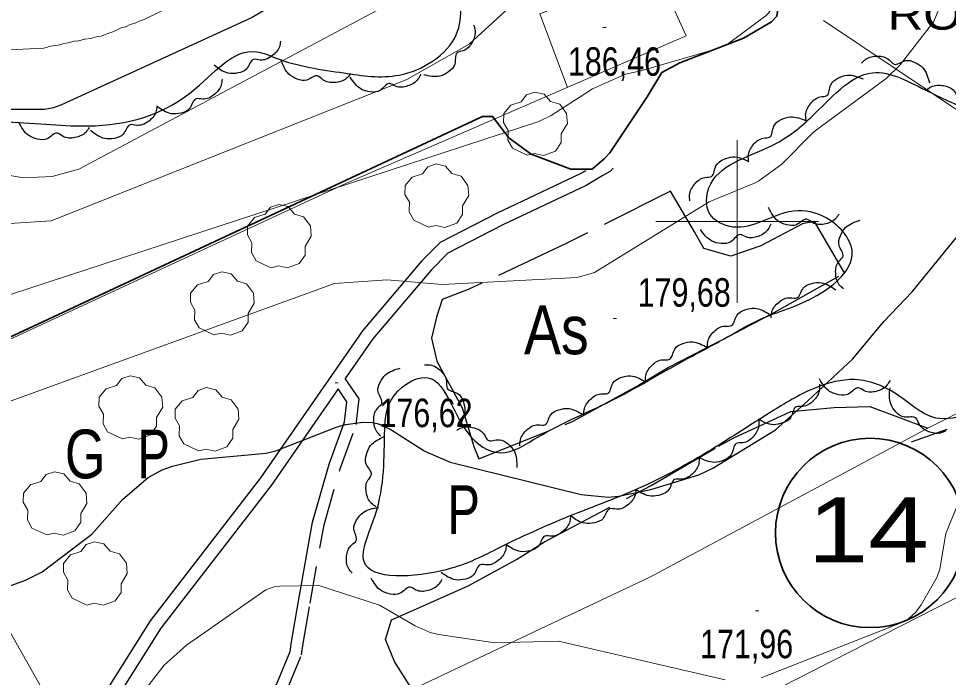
# Model space of a CAD drawing. Extents: x 483847 to 488453, y 4383581 to 4386795.
# Drawn here: x 484279 to 484564.9, y 4384859.8 to 4385062.3 of the extents above; entities that cross this region are included whole.
import ezdxf
from ezdxf.enums import TextEntityAlignment as Align

# ---------------------------------------------------------------- set-up
doc = ezdxf.new("R2010")
doc.units = 0
doc.header["$LTSCALE"] = 3.8
doc.linetypes.add('LONG_DASHED', pattern=[7.5, 6, -1.5])
doc.linetypes.add('MEDIUM_DASHED', pattern=[4.5, 3, -1.5])
for name, color, linetype, lineweight in [('1', 7, 'Continuous', 13), ('13', 7, 'Continuous', 25), ('25', 7, 'LONG_DASHED', 25), ('27', 7, 'Continuous', 25), ('29', 7, 'Continuous', 13), ('38', 7, 'Continuous', 25), ('51', 7, 'Continuous', 13), ('6', 7, 'Continuous', 35), ('7', 7, 'Continuous', 13), ('8', 7, 'Continuous', 25), ('9', 7, 'Continuous', 13)]:
    doc.layers.add(name, color=color, linetype=linetype, lineweight=lineweight)
doc.layers.add('31', color=7, linetype='Continuous')
doc.layers.add('5', color=7, linetype='Continuous')

msp = doc.modelspace()

# ---------------------------------------------------------------- linework, layer by layer
at = {"layer": '1'}
for p, q in [((484500, 4385025), (484500, 4384975)), ((484475, 4385000), (484525, 4385000))]:
    msp.add_line(p, q, dxfattribs=at)
at = {"layer": '25'}
for points in [[(484407.47, 4384970.58), (484405.96, 4384964.15), (484407.6, 4384957), (484415.4, 4384942.72), (484419.03, 4384930.85), (484420.57, 4384926.99), (484449.29, 4384938.49), (484469.13, 4384949.39), (484478.74, 4384955.04), (484497.73, 4384964.85), (484511.37, 4384971.98), (484532.95, 4384984.19), (484523.74, 4384999.93), (484520.07, 4384999.29), (484507.21, 4384992.53), (484497.98, 4384989.36), (484489.73, 4384991.68), (484486.87, 4384996.75), (484479.45, 4385009.25), (484447.21, 4384993.1), (484417.29, 4384979.02)], [(484417.29, 4384979.02), (484409.3, 4384975.94), (484407.47, 4384970.58)], [(484400.03, 4384856.08), (484394.58, 4384864.7), (484391.81, 4384871.43), (484393.69, 4384877.52), (484401.36, 4384880.88), (484417.27, 4384888.02), (484432.06, 4384896.02), (484440.68, 4384901.54), (484473.49, 4384918.81), (484494.24, 4384930.91), (484498.88, 4384933.47), (484516.48, 4384941.57), (484529.75, 4384942.8), (484540.79, 4384943.06), (484558.57, 4384936.42)]]:
    msp.add_lwpolyline(points, dxfattribs=at)
at = {"layer": '27'}
for points in [[(484126.09, 4384902.79), (484170.42, 4384940.62), (484186.72, 4384951.71), (484191.28, 4384949.75), (484195.85, 4384942.58), (484195.2, 4384850.61), (484198.46, 4384849.31), (484203.02, 4384849.96), (484206.93, 4384851.91), (484210.19, 4384864.31), (484210.19, 4384911.92), (484211.5, 4384943.23), (484214.1, 4384965.41), (484221.93, 4384987.58), (484217.36, 4384992.8), (484210.19, 4384992.8), (484135.22, 4384984.97), (484130.65, 4384988.89), (484126.09, 4384997.37), (484121.53, 4385047.59), (484126.09, 4385059.33), (484133.91, 4385067.16), (484151.52, 4385069.77), (484197.15, 4385061.94), (484225.84, 4385054.77), (484236.92, 4385050.2), (484251.92, 4385040.42), (484272.13, 4385031.28), (484285.82, 4385029.98), (484298.2, 4385029.33), (484332.11, 4385039.76), (484352.32, 4385052.16), (484358.18, 4385050.2), (484379.05, 4385045.63), (484396, 4385044.98), (484413.6, 4385057.38), (484413.6, 4385076.29), (484415.56, 4385110.21), (484421.42, 4385117.38), (484434.46, 4385125.86), (484452.06, 4385127.17), (484517.26, 4385131.08), (484535.51, 4385145.43), (484539.43, 4385153.26), (484534.21, 4385163.04), (484527.69, 4385172.17), (484530.3, 4385183.26), (484560.29, 4385234.79), (484583.76, 4385251.75), (484588.32, 4385252.4), (484664.6, 4385247.83), (484699.15, 4385252.4), (484722.1, 4385262.06)], [(484418.91, 4385060.4), (484419.36, 4385058.69), (484418.44, 4385055.01), (484415.75, 4385052.47), (484413.82, 4385051.77), (484413.13, 4385048.28), (484411.25, 4385045.96), (484408.53, 4385044.63), (484403.59, 4385045.04)], [(484359.54, 4385055.43), (484359.22, 4385053.69), (484356.82, 4385050.75), (484353.31, 4385049.59), (484351.27, 4385049.78), (484349.16, 4385046.91), (484346.47, 4385045.62), (484343.45, 4385045.56), (484339.15, 4385048.03)], [(484380.98, 4385045.23), (484379.79, 4385043.91), (484376.2, 4385042.68), (484372.61, 4385043.53), (484370.96, 4385044.76), (484367.67, 4385043.44), (484364.7, 4385043.75), (484362.1, 4385045.29), (484359.73, 4385049.65)], [(484538.21, 4385048.6), (484539.5, 4385049.83), (484543.16, 4385050.8), (484546.68, 4385049.68), (484548.23, 4385048.33), (484551.62, 4385049.42), (484554.56, 4385048.89), (484557.04, 4385047.16), (484559.08, 4385042.64)], [(484585.59, 4384948.21), (484580.97, 4384945.58), (484559.8, 4384939.88), (484549.69, 4384946.4), (484536.11, 4384951.35), (484524.15, 4384948.87), (484511.2, 4384941.93), (484493.5, 4384930.76), (484470.97, 4384918.5), (484448.03, 4384909.24), (484426.95, 4384899.71), (484410.49, 4384892.92), (484385.23, 4384895.42), (484388.62, 4384909.57), (484391.63, 4384936.1), (484393.56, 4384945.05), (484404.24, 4384952.03), (484417.14, 4384934.99), (484427.13, 4384928.88), (484438.84, 4384933.79), (484461.12, 4384944.82), (484483.93, 4384957.41), (484496.79, 4384964.37), (484506.7, 4384969.76), (484524.49, 4384977.21), (484535.34, 4384990.46), (484526.45, 4385001.52), (484515.95, 4385002.96), (484498.76, 4384998.27), (484491.46, 4385002.45), (484491.28, 4385010.27), (484510.27, 4385023.11), (484522.64, 4385031.97), (484541.56, 4385045.7), (484558.82, 4385039.91), (484572.59, 4385033.52), (484597.25, 4385020.22), (484607.27, 4385012.89), (484618.82, 4385004.61), (484624.36, 4385000.79), (484636.37, 4384994.07), (484662.16, 4385005.98), (484666.23, 4385010.44), (484675.39, 4385021.46), (484682.04, 4385029.89), (484691.36, 4385035.38), (484695.06, 4385038.96)], [(484341.58, 4385043.71), (484341.34, 4385041.95), (484339.08, 4385038.91), (484335.63, 4385037.59), (484333.58, 4385037.67), (484331.6, 4385034.72), (484328.98, 4385033.3), (484325.96, 4385033.1), (484321.55, 4385035.37)], [(484402.63, 4385045.27), (484401.8, 4385043.7), (484398.63, 4385041.62), (484394.94, 4385041.57), (484393.04, 4385042.36), (484390.17, 4385040.26), (484387.22, 4385039.83), (484384.32, 4385040.68), (484380.95, 4385044.33)], [(484521.2, 4385030.91), (484521.01, 4385032.67), (484522.48, 4385036.17), (484525.52, 4385038.27), (484527.53, 4385038.68), (484528.74, 4385042.02), (484530.95, 4385044.03), (484533.83, 4385044.94), (484538.66, 4385043.79)], [(484558.14, 4385040.38), (484559.61, 4385041.38), (484563.38, 4385041.73), (484566.67, 4385040.05), (484567.98, 4385038.47), (484571.49, 4385038.98), (484574.31, 4385037.97), (484576.47, 4385035.86), (484577.73, 4385031.07)], [(484321.57, 4385035.35), (484321.25, 4385033.6), (484318.85, 4385030.66), (484315.34, 4385029.51), (484313.3, 4385029.69), (484311.19, 4385026.82), (484308.5, 4385025.52), (484305.48, 4385025.47), (484301.18, 4385027.93)], [(484503.54, 4385018.29), (484503.38, 4385020.06), (484504.9, 4385023.54), (484507.97, 4385025.59), (484509.99, 4385025.97), (484511.25, 4385029.29), (484513.49, 4385031.27), (484516.38, 4385032.14), (484521.19, 4385030.92)], [(484300.77, 4385028.91), (484299.76, 4385027.45), (484296.37, 4385025.75), (484292.7, 4385026.12), (484290.9, 4385027.12), (484287.81, 4385025.37), (484284.83, 4385025.28), (484282.04, 4385026.46), (484279.12, 4385030.47)], [(484485.44, 4385006.32), (484485.32, 4385008.1), (484486.94, 4385011.53), (484490.06, 4385013.5), (484492.09, 4385013.82), (484493.44, 4385017.11), (484495.73, 4385019.02), (484498.65, 4385019.81), (484503.43, 4385018.46)], [(484531.22, 4385002.21), (484530.18, 4385000.77), (484526.75, 4384999.15), (484523.09, 4384999.61), (484521.32, 4385000.65), (484518.18, 4384998.98), (484515.2, 4384998.96), (484512.45, 4385000.21), (484509.62, 4385004.28)], [(484532.63, 4384979.27), (484531.36, 4384980.5), (484530.24, 4384984.13), (484531.21, 4384987.69), (484532.5, 4384989.29), (484531.28, 4384992.63), (484531.68, 4384995.59), (484533.31, 4384998.14), (484537.74, 4385000.36)], [(484510.29, 4384999.16), (484509.51, 4384997.56), (484506.41, 4384995.38), (484502.72, 4384995.21), (484500.8, 4384995.93), (484498, 4384993.74), (484495.06, 4384993.21), (484492.14, 4384993.97), (484488.65, 4384997.5)], [(484510.37, 4384970.36), (484510.6, 4384972.12), (484512.83, 4384975.19), (484516.26, 4384976.55), (484518.31, 4384976.48), (484520.25, 4384979.46), (484522.87, 4384980.91), (484525.88, 4384981.14), (484530.32, 4384978.92)], [(484490.85, 4384961.14), (484490.91, 4384962.92), (484492.85, 4384966.18), (484496.15, 4384967.84), (484498.2, 4384967.97), (484499.86, 4384971.11), (484502.32, 4384972.79), (484505.3, 4384973.3), (484509.92, 4384971.5)], [(484471.81, 4384950.73), (484471.86, 4384952.51), (484473.78, 4384955.78), (484477.07, 4384957.46), (484479.12, 4384957.6), (484480.76, 4384960.75), (484483.21, 4384962.45), (484486.19, 4384962.97), (484490.82, 4384961.2)], [(484390.41, 4384934.03), (484389.19, 4384935.32), (484388.22, 4384938.99), (484389.34, 4384942.5), (484390.69, 4384944.05), (484389.6, 4384947.44), (484390.13, 4384950.38), (484391.86, 4384952.86), (484396.38, 4384954.9)], [(484403.78, 4384955.9), (484405.56, 4384955.88), (484408.86, 4384954.02), (484410.6, 4384950.77), (484410.77, 4384948.72), (484413.95, 4384947.13), (484415.69, 4384944.7), (484416.26, 4384941.73), (484414.57, 4384937.07)], [(484452.82, 4384940.23), (484452.87, 4384942.01), (484454.78, 4384945.28), (484458.07, 4384946.97), (484460.12, 4384947.11), (484461.75, 4384950.27), (484464.21, 4384951.97), (484467.18, 4384952.49), (484471.82, 4384950.72)], [(484546.95, 4384951.14), (484546.02, 4384949.63), (484542.73, 4384947.75), (484539.04, 4384947.93), (484537.2, 4384948.84), (484534.2, 4384946.93), (484531.23, 4384946.68), (484528.38, 4384947.72), (484525.26, 4384951.57)], [(484525.27, 4384949.95), (484525.25, 4384948.17), (484523.37, 4384944.87), (484520.11, 4384943.14), (484518.07, 4384942.98), (484516.47, 4384939.8), (484514.04, 4384938.07), (484511.07, 4384937.5), (484506.41, 4384939.21)], [(484564.13, 4384935.62), (484562.49, 4384934.95), (484558.72, 4384935.41), (484555.87, 4384937.75), (484554.92, 4384939.57), (484551.38, 4384939.82), (484548.84, 4384941.39), (484547.17, 4384943.91), (484546.95, 4384948.87)], [(484433.15, 4384931.05), (484433.29, 4384932.82), (484435.39, 4384935.98), (484438.76, 4384937.48), (484440.82, 4384937.5), (484442.63, 4384940.56), (484445.17, 4384942.12), (484448.18, 4384942.48), (484452.7, 4384940.45)], [(484506.57, 4384938.96), (484506.62, 4384937.18), (484504.89, 4384933.81), (484501.7, 4384931.94), (484499.66, 4384931.69), (484498.2, 4384928.45), (484495.85, 4384926.61), (484492.9, 4384925.92), (484488.18, 4384927.43)], [(484413.72, 4384935.75), (484415.28, 4384936.58), (484419.08, 4384936.52), (484422.16, 4384934.49), (484423.29, 4384932.78), (484426.84, 4384932.9), (484429.53, 4384931.6), (484431.45, 4384929.26), (484432.19, 4384924.36)], [(484388.89, 4384912.28), (484387.47, 4384913.35), (484385.91, 4384916.81), (484386.45, 4384920.46), (484387.52, 4384922.21), (484385.9, 4384925.37), (484385.95, 4384928.36), (484387.25, 4384931.09), (484391.38, 4384933.83)], [(484488.24, 4384927.29), (484488.14, 4384925.52), (484486.11, 4384922.31), (484482.77, 4384920.74), (484480.72, 4384920.67), (484478.98, 4384917.57), (484476.47, 4384915.96), (484473.47, 4384915.53), (484468.9, 4384917.46)], [(484468.85, 4384917.57), (484468.58, 4384915.81), (484466.28, 4384912.8), (484462.81, 4384911.53), (484460.76, 4384911.65), (484458.74, 4384908.72), (484456.1, 4384907.34), (484453.08, 4384907.19), (484448.7, 4384909.52)], [(484381.56, 4384891.95), (484380.47, 4384893.36), (484379.88, 4384897.11), (484381.36, 4384900.49), (484382.86, 4384901.89), (484382.13, 4384905.37), (484382.96, 4384908.24), (484384.93, 4384910.53), (484389.64, 4384912.09)], [(484448.69, 4384909.54), (484448.5, 4384907.77), (484446.32, 4384904.66), (484442.91, 4384903.25), (484440.86, 4384903.28), (484438.97, 4384900.27), (484436.38, 4384898.78), (484433.37, 4384898.5), (484428.9, 4384900.64)], [(484428.93, 4384900.56), (484428.71, 4384898.79), (484426.47, 4384895.73), (484423.03, 4384894.39), (484420.98, 4384894.46), (484419.03, 4384891.49), (484416.41, 4384890.05), (484413.4, 4384889.83), (484408.97, 4384892.06)], [(484409.11, 4384889.93), (484408.19, 4384888.42), (484404.9, 4384886.53), (484401.21, 4384886.69), (484399.37, 4384887.59), (484396.38, 4384885.67), (484393.4, 4384885.41), (484390.56, 4384886.44), (484387.42, 4384890.28)]]:
    msp.add_spline(points, degree=3, dxfattribs=at)
at = {"layer": '29'}
for points in [[(484435.38, 4385020.34), (484430.84, 4385022.46), (484429.43, 4385025), (484429.53, 4385027.98), (484428.16, 4385030.39), (484428.2, 4385033.14), (484430.36, 4385035.74), (484433.55, 4385036.74), (484435.2, 4385038.93), (484437.77, 4385039.76), (484440.63, 4385039.11), (484442.58, 4385036.84), (484445.39, 4385036.02), (484447.52, 4385033.17), (484447.76, 4385030.04), (484445.88, 4385026.89), (484445.88, 4385024.21), (484444.06, 4385021.6), (484440.44, 4385020.26), (484437.67, 4385020.89)], [(484405.05, 4384998.23), (484400.51, 4385000.35), (484399.1, 4385002.89), (484399.2, 4385005.87), (484397.83, 4385008.28), (484397.87, 4385011.03), (484400.03, 4385013.63), (484403.22, 4385014.63), (484404.87, 4385016.82), (484407.44, 4385017.65), (484410.3, 4385017), (484412.25, 4385014.73), (484415.06, 4385013.91), (484417.19, 4385011.06), (484417.43, 4385007.93), (484415.55, 4385004.78), (484415.55, 4385002.1), (484413.73, 4384999.49), (484410.11, 4384998.15), (484407.34, 4384998.78)], [(484356.63, 4384985.77), (484352.09, 4384987.89), (484350.68, 4384990.43), (484350.78, 4384993.41), (484349.41, 4384995.82), (484349.45, 4384998.57), (484351.61, 4385001.17), (484354.8, 4385002.17), (484356.45, 4385004.36), (484359.02, 4385005.19), (484361.88, 4385004.54), (484363.83, 4385002.27), (484366.64, 4385001.45), (484368.77, 4384998.6), (484369.01, 4384995.47), (484367.13, 4384992.32), (484367.13, 4384989.64), (484365.31, 4384987.03), (484361.69, 4384985.69), (484358.92, 4384986.32)], [(484339.1, 4384965.12), (484334.56, 4384967.24), (484333.15, 4384969.78), (484333.25, 4384972.76), (484331.88, 4384975.17), (484331.92, 4384977.92), (484334.08, 4384980.52), (484337.27, 4384981.52), (484338.92, 4384983.71), (484341.49, 4384984.54), (484344.35, 4384983.89), (484346.3, 4384981.62), (484349.11, 4384980.8), (484351.24, 4384977.95), (484351.48, 4384974.82), (484349.6, 4384971.67), (484349.6, 4384968.99), (484347.78, 4384966.38), (484344.16, 4384965.04), (484341.39, 4384965.67)], [(484310.95, 4384933.15), (484306.41, 4384935.27), (484305, 4384937.81), (484305.1, 4384940.79), (484303.73, 4384943.2), (484303.77, 4384945.95), (484305.93, 4384948.55), (484309.12, 4384949.55), (484310.77, 4384951.74), (484313.34, 4384952.57), (484316.2, 4384951.92), (484318.15, 4384949.65), (484320.96, 4384948.83), (484323.09, 4384945.98), (484323.33, 4384942.85), (484321.45, 4384939.7), (484321.45, 4384937.02), (484319.63, 4384934.41), (484316.01, 4384933.07), (484313.24, 4384933.7)], [(484334.39, 4384929.47), (484329.85, 4384931.59), (484328.44, 4384934.13), (484328.54, 4384937.11), (484327.17, 4384939.52), (484327.21, 4384942.27), (484329.37, 4384944.87), (484332.56, 4384945.87), (484334.21, 4384948.06), (484336.78, 4384948.89), (484339.64, 4384948.24), (484341.59, 4384945.97), (484344.4, 4384945.15), (484346.53, 4384942.3), (484346.77, 4384939.17), (484344.89, 4384936.02), (484344.89, 4384933.34), (484343.07, 4384930.73), (484339.45, 4384929.39), (484336.68, 4384930.02)], [(484287.68, 4384903.63), (484283.14, 4384905.75), (484281.73, 4384908.29), (484281.83, 4384911.27), (484280.46, 4384913.68), (484280.5, 4384916.43), (484282.66, 4384919.03), (484285.85, 4384920.03), (484287.5, 4384922.22), (484290.07, 4384923.05), (484292.93, 4384922.4), (484294.88, 4384920.13), (484297.69, 4384919.31), (484299.82, 4384916.46), (484300.06, 4384913.33), (484298.18, 4384910.18), (484298.18, 4384907.5), (484296.36, 4384904.89), (484292.74, 4384903.55), (484289.97, 4384904.18)], [(484300.02, 4384882.08), (484295.48, 4384884.2), (484294.07, 4384886.74), (484294.17, 4384889.72), (484292.8, 4384892.13), (484292.84, 4384894.88), (484295, 4384897.48), (484298.19, 4384898.48), (484299.84, 4384900.67), (484302.41, 4384901.5), (484305.27, 4384900.85), (484307.22, 4384898.58), (484310.03, 4384897.76), (484312.16, 4384894.91), (484312.4, 4384891.78), (484310.52, 4384888.63), (484310.52, 4384885.95), (484308.7, 4384883.34), (484305.08, 4384882), (484302.31, 4384882.63)]]:
    msp.add_lwpolyline(points, close=True, dxfattribs=at)
at = {"layer": '38'}
for points in [[(484453.38, 4385015.57), (484451.7, 4385014.58), (484426.16, 4385002.56), (484408.6, 4384993.5), (484402.92, 4384987.73), (484384.78, 4384966.36), (484353.42, 4384921.22), (484319.47, 4384877.26), (484293.44, 4384835.87), (484288.43, 4384826.81), (484285.53, 4384814.9), (484285.91, 4384805.4), (484286.07, 4384803.76)], [(484461.86, 4385016.32), (484461.03, 4385015.4), (484458.68, 4385014.09), (484453.57, 4385011.05), (484427.92, 4384998.98), (484410.99, 4384990.25), (484405.86, 4384985.04), (484387.94, 4384963.93), (484379.46, 4384951.72)], [(484377.24, 4384948.53), (484356.64, 4384918.86), (484322.74, 4384874.97), (484296.87, 4384833.84), (484292.17, 4384825.35), (484289.53, 4384814.5), (484289.89, 4384805.68), (484290.04, 4384804.14)], [(484321.36, 4384816.53), (484351.98, 4384849.58), (484358.35, 4384857.61), (484362.54, 4384867.77), (484362.98, 4384870.8), (484365.1, 4384883.31), (484369.39, 4384907.59), (484374.51, 4384925.34), (484379.23, 4384938.39), (484379.98, 4384944.57), (484377.24, 4384948.53)]]:
    msp.add_lwpolyline(points, dxfattribs=at)
at = {"layer": '38', "linetype": 'MEDIUM_DASHED'}
msp.add_lwpolyline([(484324.02, 4384814.06), (484354.73, 4384847.21), (484361.52, 4384855.75), (484366.06, 4384866.8), (484366.57, 4384870.24), (484368.68, 4384882.69), (484372.93, 4384906.77), (484377.96, 4384924.22), (484382.79, 4384937.55), (484383.75, 4384945.5), (484379.46, 4384951.72)], dxfattribs=at)
at = {"layer": '51'}
for points in [[(484484.3, 4385057.04), (484474.99, 4385077.67), (484439.24, 4385063.79), (484447.79, 4385041.2)], [(484526.51, 4385061.76), (484636.63, 4384988), (484717.12, 4384856.42)], [(484484.3, 4385057.04), (484379.62, 4385011.61), (484236.15, 4384945.17), (484295.85, 4384839.28)], [(484635.97, 4384988.45), (484600.12, 4384957.29), (484558.58, 4384936.42), (484473.09, 4384890.68), (484400.03, 4384856.08)], [(484481.98, 4384840.82), (484586.98, 4384894.3), (484572.68, 4384921.94)]]:
    msp.add_lwpolyline(points, dxfattribs=at)
at = {"layer": '6', "lineweight": 25}
msp.add_line((484553.52, 4384932.19), (484564.48, 4384936.17), dxfattribs=at)
at = {"layer": '6'}
for points in [[(484512.97, 4385071.07), (484512.88, 4385067.92), (484512.1, 4385063.1), (484510.53, 4385061.38), (484505.04, 4385058.19), (484501.9, 4385056.36), (484482.31, 4385048.73), (484476.84, 4385045.76), (484472.32, 4385038.32), (484460.76, 4385021.04), (484459.08, 4385019.18)], [(484459.08, 4385019.18), (484455.39, 4385016.01), (484448.82, 4385016.01), (484436.64, 4385020.7), (484429.76, 4385025.69), (484424.76, 4385032.25), (484421.64, 4385032.25), (484282.12, 4384967.05), (484265.88, 4384959.56), (484249.94, 4384952.38), (484246.29, 4384952.07), (484240.98, 4384954.25), (484237.23, 4384962.37)]]:
    msp.add_lwpolyline(points, dxfattribs=at)
msp.add_circle((484540.83, 4384904.23), 29.1, dxfattribs=at)
at = {"layer": '7'}
for p, q in [((484458.67, 4385059.63), (484459.67, 4385059.63)), ((484461.85, 4384970.14), (484462.85, 4384970.14)), ((484376.31, 4384950.39), (484377.31, 4384950.39)), ((484505.58, 4384880.32), (484506.58, 4384880.32))]:
    msp.add_line(p, q, dxfattribs=at)
at = {"layer": '8'}
for points in [[(484370.39, 4385170.61), (484369.7, 4385169.67), (484369.64, 4385169.57), (484370.26, 4385168.07), (484370.6, 4385167.5), (484371.87, 4385166.08), (484382, 4385158.12), (484387.33, 4385152.5), (484388.19, 4385151.36), (484399.07, 4385130.26), (484399.4, 4385128.77), (484399.72, 4385112.17), (484399.49, 4385110.37), (484399.06, 4385108.68), (484398.74, 4385107.8), (484388.2, 4385090.22), (484379.02, 4385079.4), (484350.89, 4385062.64), (484292.17, 4385035.78), (484289.71, 4385034.93), (484286.97, 4385034.4), (484273.13, 4385034.35)], [(484473.46, 4384917.59), (484488.17, 4384922.06), (484492.47, 4384924.15), (484511.78, 4384935.95), (484521.68, 4384944.86), (484535.56, 4384957.76), (484545.01, 4384969.26), (484553.81, 4384978.38), (484571.75, 4385000.45)], [(484270.06, 4384885.77), (484281.11, 4384889.71), (484286.25, 4384892.3), (484301.58, 4384903.87), (484311.06, 4384914.59), (484318.88, 4384921.28), (484323.13, 4384923.58), (484326.31, 4384924.79), (484335.05, 4384926.86), (484355.19, 4384928.72), (484358.08, 4384929.46), (484377.01, 4384936.85), (484379.65, 4384937.6), (484384.84, 4384938.26), (484387.8, 4384938.17), (484389.27, 4384937.88), (484390.22, 4384937.57), (484393.44, 4384936.03), (484393.47, 4384936), (484393.48, 4384935.99), (484403.46, 4384929.67), (484403.54, 4384929.61), (484404.8, 4384928.92), (484411.68, 4384926.02), (484451.97, 4384916), (484460.3, 4384915.25), (484463.48, 4384915.51), (484473.46, 4384917.59)]]:
    msp.add_lwpolyline(points, dxfattribs=at)
at = {"layer": '9'}
for points in [[(484453.3, 4385097.31), (484451.93, 4385098.08), (484451.54, 4385098.24), (484450.84, 4385098.43), (484450.17, 4385098.42), (484450.01, 4385098.38), (484449.85, 4385098.31), (484449.36, 4385097.91), (484448.95, 4385097.33), (484448.77, 4385096.97), (484448.52, 4385096.25), (484448.46, 4385095.07), (484449.83, 4385087.37), (484449.81, 4385086.39), (484449.48, 4385084.26), (484448.9, 4385082.52), (484447.65, 4385080.21), (484444.97, 4385076.84), (484443.01, 4385075.11), (484430.83, 4385066.67), (484417.55, 4385054.47), (484398.37, 4385043.6), (484289.05, 4385000.17), (484242.69, 4384997.21)], [(484566.35, 4385076.26), (484560.4, 4385061.4), (484550.03, 4385048.09), (484545.76, 4385043.92), (484523.57, 4385027.56), (484513.66, 4385017.54), (484506.61, 4385012.45), (484505.33, 4385011.73), (484491.34, 4385006.06), (484456.12, 4384984.29), (484450.77, 4384982.8), (484409.36, 4384980.56), (484392.26, 4384982.07), (484376.13, 4384980.87), (484228.37, 4384927.37)], [(484246.15, 4384967.85), (484247.65, 4384968.12), (484438.96, 4385030.72), (484442.78, 4385032.54), (484453.15, 4385039.21), (484455.46, 4385040.7), (484465.61, 4385045.22), (484470.29, 4385046.25), (484494, 4385053.14), (484497.33, 4385054.72), (484508.86, 4385063.24), (484509.55, 4385063.96), (484510.43, 4385065.35), (484511.21, 4385067.08), (484511.22, 4385067.1), (484511.22, 4385067.16), (484511.8, 4385069.58), (484511.9, 4385074.36)], [(484409.77, 4385075.87), (484297.56, 4385016.02), (484289.39, 4385013.78), (484280.58, 4385013.34)], [(484273.97, 4385052.67), (484286.84, 4385053.27), (484288.82, 4385053.87), (484291.25, 4385054.21), (484292.89, 4385054.67), (484294.3, 4385054.87), (484296.1, 4385055.35), (484297.47, 4385055.51), (484297.64, 4385055.54), (484299.14, 4385056.01), (484299.35, 4385056.05), (484301.18, 4385056.22), (484301.59, 4385056.29), (484303.02, 4385056.74), (484304.43, 4385056.96), (484304.64, 4385057.02), (484306.73, 4385057.85), (484307.97, 4385058.22), (484310.56, 4385059.47), (484311.85, 4385059.79), (484312.16, 4385059.89), (484313.36, 4385060.48), (484314.77, 4385060.88), (484315.08, 4385061), (484316.11, 4385061.55), (484317.6, 4385062.1), (484337.33, 4385071.75)], [(484507.37, 4384859.73), (484551.37, 4384876.96), (484552.77, 4384877.94), (484554.87, 4384879.92), (484556.57, 4384882.14), (484561.49, 4384890.74), (484562.24, 4384893.05), (484564.15, 4384904.01), (484568.91, 4384915.8), (484569.85, 4384921.83), (484570.51, 4384923.41), (484576.94, 4384934.93), (484582.28, 4384940.48), (484620.44, 4384987.15), (484626.11, 4385004.03), (484627.56, 4385006.48), (484628.56, 4385007.65), (484629.35, 4385008.33), (484629.62, 4385008.52), (484631.06, 4385009.35), (484632.76, 4385010), (484642.78, 4385012.43), (484644.37, 4385013.07), (484724.63, 4385058.95)], [(484280.58, 4385013.34), (484244.45, 4385019.59), (484236.7, 4385021.97), (484234.99, 4385022.73), (484232.53, 4385024.03), (484231.85, 4385024.3), (484230.57, 4385024.61), (484229.45, 4385024.77), (484198.47, 4385022.19), (484157.26, 4385026.74), (484102.46, 4385042.34)], [(484302.84, 4384836.69), (484323.82, 4384863.59), (484330.64, 4384869.72), (484355.02, 4384886.73), (484357.56, 4384887.64), (484359.36, 4384887.91), (484371.38, 4384888.05), (484390.04, 4384882.06), (484400.96, 4384875.68), (484405.57, 4384873.66), (484408.27, 4384872.98), (484425.45, 4384870.41), (484445.05, 4384870.92), (484496.26, 4384859.12)]]:
    msp.add_lwpolyline(points, dxfattribs=at)

# ---------------------------------------------------------------- texts
at = {"layer": '13', "width": 1.25}
msp.add_text('14', height=20, dxfattribs=at).set_placement((484540.28, 4384895.2), align=Align.CENTER)
at = {"layer": '31'}
for s, width, p in [('As', 0.85, (484444.36, 4384959.16)), ('G', 0.8, (484299.5, 4384921.01)), ('P', 0.75, (484320.54, 4384921)), ('P', 0.75, (484415.86, 4384903.88))]:
    msp.add_text(s, height=15, dxfattribs=dict(at, width=width)).set_placement(p, align=Align.CENTER)
at = {"layer": '5', "width": 1.2}
msp.add_text("ROTA D'EN BUSQUET", height=9.5, dxfattribs=at).set_placement((484546.18, 4385058.94))
at = {"layer": '7', "width": 0.8}
for s, p in [('186,46', (484447.91, 4385044.76)), ('179,68', (484469.35, 4384973.79)), ('176,62', (484389.98, 4384936.75)), ('171,96', (484488.54, 4384865.72))]:
    msp.add_text(s, height=8.75, dxfattribs=at).set_placement(p)

doc.saveas('drawing.dxf')
